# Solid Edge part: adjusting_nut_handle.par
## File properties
Title: Adjusting nut handle
Author: Abhinav Rai
Template: Normal.par
Last saved by: Rajat Kamboj
Revision: 17
Application: Solid Edge
Accuracy: 0.99
Material: aluminum
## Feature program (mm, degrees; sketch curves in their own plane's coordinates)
sketch for "unnamed Protrusion 1" plane through (0, 0, 0) normal (0, -1, 0) x-axis (1, 0, 0)
  circle centre (0, 0) radius 9.5123
extrude "unnamed Protrusion 1" add finite 127 symmetric
chamfer "Chamfer_1" setback 1.5748
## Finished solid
Body 1: solid body, 5 faces, 4 edges, 0 vertices.
  Faces by surface: cone 2, plane 2, cylinder 1
  Edges by curve: circle 4
Bounding box of the edges (mm): 19.025 x 127.000 x 19.025, from (-9.5123, -63.5, -9.5123) to (9.5123, 63.5, 9.5123).
Cylindrical faces by radius (mm): R9.5123 x1
Conical faces (half-angle, radius in mm at the cone's reference point): 45 deg R7.9375 x1, 45 deg R9.5123 x1
Planar faces by outward normal: +y 1, -y 1
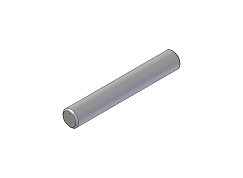
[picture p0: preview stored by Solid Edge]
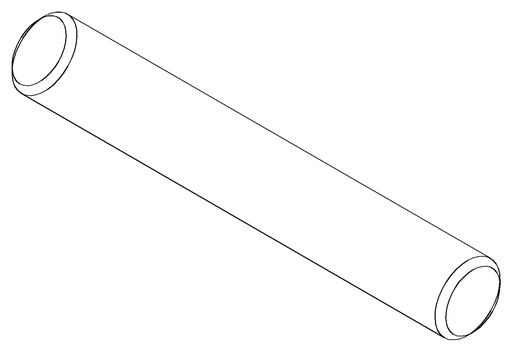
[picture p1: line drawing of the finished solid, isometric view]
